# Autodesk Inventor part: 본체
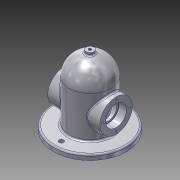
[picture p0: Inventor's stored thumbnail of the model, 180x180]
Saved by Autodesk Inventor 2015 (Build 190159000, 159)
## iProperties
Created: 2019-11
Part Number: 본체
Material: 알루미늄 6061
Document SubType Name: Modeling
Designer: Lineart
Density: 2.7 g/cm^3
Appearance: 알루미늄 - 평지
Mass: 1106.52 g
Surface Area: 886.269 cm^2
Volume: 409.823 cm^3
Author: Lineart
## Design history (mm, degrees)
sketch "스케치1"
  geometry: C1 r 70 at (0, 0); 1 further point
  constraints: 1 centre point, 1 coincident
  dimensions: "d0" = 70 radius of C1
extrude "돌출1" new body sketch "스케치1" distance "d1" = 10; taper "d2" = 0 deg
sketch "스케치2"
  geometry: C1 r 40 at (0, 0); 1 further point
  constraints: 1 centre point, 1 coincident
  dimensions: "d3" = 40 radius of C1
extrude "돌출2" join sketch "스케치2" distance "d4" = 80; taper "d5" = 0 deg
sketch "스케치3"
  geometry: L1 (40, 90)-(-40, 90) reference; L2 (0, 130)-(0, 90); L3 (40, 90)-(0, 90); A1 r 40 centre (0, 90) between (40, 90) and (0, 130); 1 further point
  constraints: 4 end point, 2 point on circle, 1 centre point, 1 collinear, 1 midpoint, 1 vertical
revolve "회전1" sketch "스케치3" stored, may be unused: angle "d6" = 90 deg
node "작업 평면1"
sketch "스케치4"
  geometry: C1 r 7.5 at (0, 0); 1 further point
  constraints: 1 centre point, 1 coincident
  dimensions: "d8" = 7.5 radius of C1
extrude "돌출3" join sketch "스케치4" distance "d9" = 45; taper "d10" = 0 deg
sketch "스케치5"
  geometry: C1 r 70 at (0, 0) reference; 3 further points
  constraints: 2 vertical alignment
  dimensions: "d11" = 55 distance of point (0, 0) point (0, 55); "d12" = 110 distance of point (0, -55) point (0, 55)
hole "구멍1" sketch "스케치5" at (0, 55), (0, -55) diameter "d13" = 9; stored, may be unused: countersink angle "d17" = 90 deg, drill point angle "d19" = 118 deg; dims "d14" = 6, "d15" = 4, "d16" = 2, "d18" = 8
sketch "스케치6"
  geometry: C1 r 7.5 at (0, 0) reference; C2 r 30 at (0, 0); 1 further point
  constraints: 1 centre point, 1 coincident
  dimensions: "d20" = 30 radius of C2
extrude "돌출4" cut sketch "스케치6" distance "d21" = 90; taper "d22" = 0 deg
sketch "스케치7"
  geometry: L1 (30, 90)-(-30, 90) reference; L2 (-30, 90)-(0, 90); L3 (0, 120)-(0, 90); A1 r 30 centre (0, 90) between (0, 120) and (-30, 90); 1 further point
  constraints: 4 end point, 2 point on circle, 1 centre point, 1 collinear, 1 midpoint, 1 perpendicular
revolve "회전2" sketch "스케치7" stored, may be unused: angle "d23" = 90 deg
sketch "스케치8"
  geometry: L1 (40, 90)-(-40, 90) reference; L2 (-40, 10)-(40, 10) reference; L3 (40, 10)-(40, 90) reference; L4 (-40, 10)-(-40, 90) reference; C1 r 31 at (0, 50); 1 further point
  constraints: 1 centre point
  dimensions: "d24" = 31 radius of C1; "d25" = 50 distance of point (0, 0) C1.centre; "d26" = 40 distance from line of L3 C1.centre
extrude "돌출5" join sketch "스케치8" stored distance "d27" = 100; taper "d28" = 0 deg
sketch "스케치9"
  geometry: C1 r 31 at (0, 0) reference; C2 r 20 at (0, 0); 1 further point
  constraints: 1 centre point, 1 coincident
  dimensions: "d29" = 20 radius of C2
extrude "돌출6" cut sketch "스케치9" distance "d30" = 15; taper "d31" = 0 deg
sketch "스케치10"
  geometry: C1 r 31 at (0, 0) reference; C2 r 16.5 at (0, 0); 1 further point
  constraints: 1 centre point, 1 coincident
  dimensions: "d32" = 16.5 radius of C2
extrude "돌출7" cut sketch "스케치10" distance "d33" = 35; taper "d34" = 0 deg
sketch "스케치11"
  geometry: C1 r 30 at (0, 0) reference; 1 further point
extrude "돌출8" cut sketch "스케치11" distance "d35" = 90; taper "d36" = 0 deg
sketch "스케치12"
  geometry: C1 r 7.5 at (0, 0) reference; 2 further points
  constraints: 1 coincident
hole "구멍2" sketch "스케치12" at (0, 0) diameter "d37" = 5.188; stored, may be unused: countersink angle "d41" = 90 deg, drill point angle "d43" = 118 deg; dims "d38" = 30, "d39" = 4, "d40" = 2, "d42" = 16
sketch "스케치13"
  geometry: L1 (-40, 40)-(-40, -40) reference; L2 (40, -40)-(40, 40) reference; L3 (40, 40)-(-40, 40) reference; L4 (40, -40)-(-40, -40) reference; L5 (50, 70)-(40, 70) reference; C1 r 31 at (0, 0) reference; 7 further points
  constraints: 7 other
  dimensions: "d44" = 26 distance of point (-26, 0) C1.centre; "d45" = 40 distance from line of L3 point (-26, 0); "d48" = 360 deg dimension on C1.centre point (-26, 0) (derived)
hole "구멍3" sketch "스케치13" at (-26, 0), (0, -26), (26, 0), (0, 26) diameter "d50" = 3.242; stored, may be unused: countersink angle "d54" = 90 deg, drill point angle "d56" = 118 deg; dims "d51" = 8, "d52" = 4, "d53" = 2, "d55" = 10
fillet "모깎기1" dims "d57" = 3, "d62" = 0.3
node "작업 평면2"
sketch "스케치14"
  geometry: L1 (-70, -10)-(70, -10) reference; L2 (50, 9)-(50, 71) reference; 2 further points
  constraints: 1 other
  dimensions: "d58" = 50 distance from line of L1 point (0, 40); "d59" = 50 distance from line of L2 point (0, 40)
feature "엠보싱1" sketch "스케치14" dims "d60" = 0.5, "d61" = 0
node "솔리드1"
mirror "대칭1"
mirror "대칭2"
node "투영된 루프1"
node "투영된 루프2"
node "투영된 루프3"
